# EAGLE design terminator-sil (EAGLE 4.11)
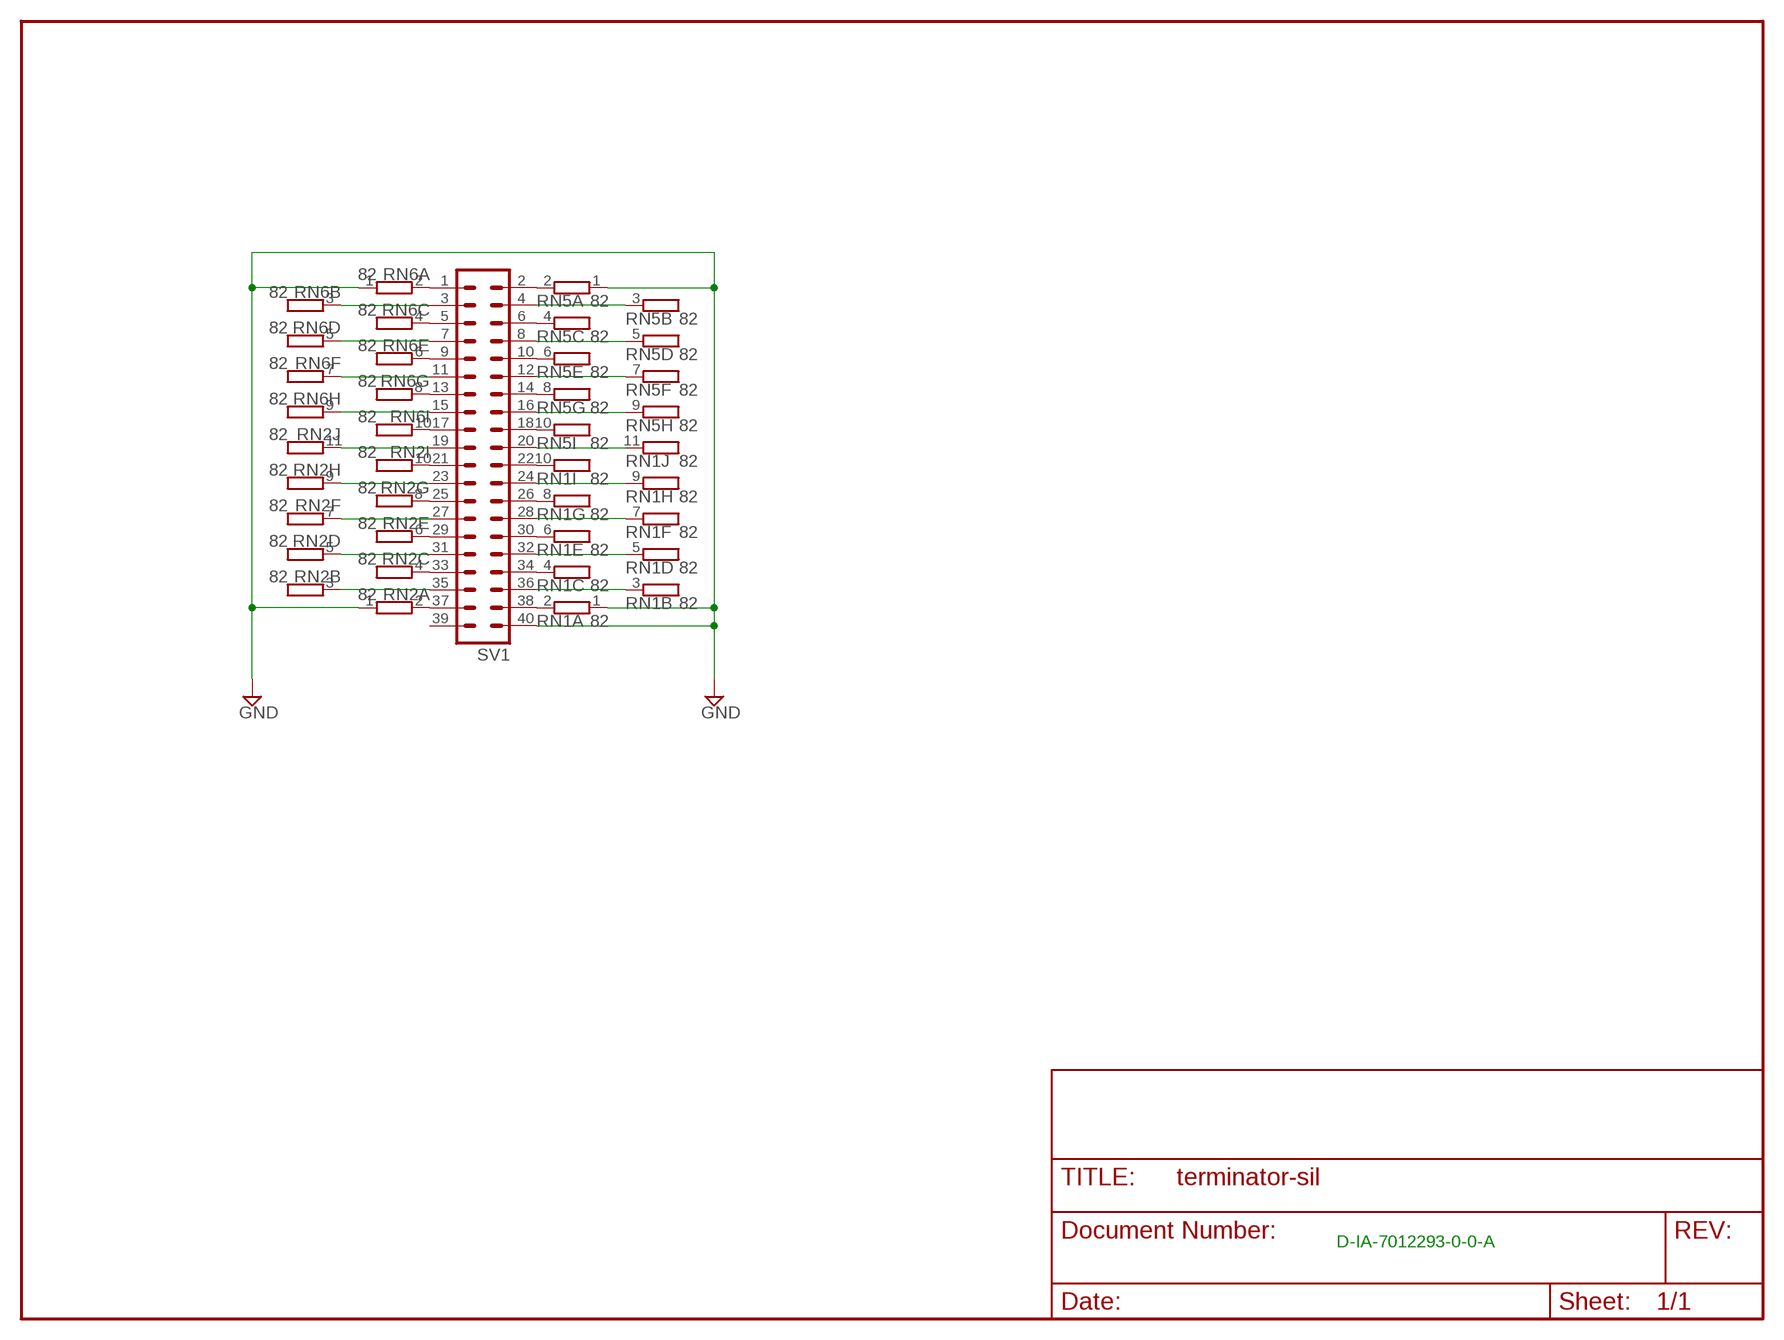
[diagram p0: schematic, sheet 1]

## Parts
RN1  82  GE10R  [SIL11]
RN2  82  GE10R  [SIL11]
RN5  82  GE09R  [SIL10]
RN6  82  GE09R  [SIL10]
SV1  MA20-2  [MA20-2]

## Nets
GND: RN1.1 RN2.1 RN5.1 RN6.1 SV1.40
N$1: RN1.2 SV1.38
N$2: RN1.3 SV1.36
N$3: RN1.4 SV1.34
N$4: RN1.6 SV1.30
N$5: RN1.8 SV1.26
N$6: RN1.10 SV1.22
N$7: RN5.10 SV1.18
N$8: RN5.8 SV1.14
N$9: RN5.6 SV1.10
N$10: RN5.4 SV1.6
N$11: RN5.3 SV1.4
N$12: RN1.5 SV1.32
N$13: RN1.7 SV1.28
N$14: RN1.9 SV1.24
N$15: RN1.11 SV1.20
N$16: RN5.9 SV1.16
N$17: RN5.7 SV1.12
N$18: RN5.5 SV1.8
N$19: RN5.2 SV1.2
N$20: RN2.2 SV1.37
N$21: RN2.4 SV1.33
N$22: RN2.6 SV1.29
N$23: RN2.8 SV1.25
N$24: RN2.10 SV1.21
N$25: RN6.10 SV1.17
N$26: RN6.8 SV1.13
N$27: RN6.6 SV1.9
N$28: RN6.4 SV1.5
N$29: RN6.2 SV1.1
N$31: RN6.3 SV1.3
N$32: RN6.5 SV1.7
N$33: RN6.7 SV1.11
N$34: RN6.9 SV1.15
N$35: RN2.3 SV1.35
N$36: RN2.5 SV1.31
N$37: RN2.7 SV1.27
N$38: RN2.9 SV1.23
N$39: RN2.11 SV1.19
Unconnected: SV1.39

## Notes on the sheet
- D-IA-7012293-0-0-A

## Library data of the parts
RN1 RN2 = resistor-sil:GE10R: SIL RESISTOR
RN5 RN6 = resistor-sil:GE09R: SIL RESISTOR
SV1 = con-lstb:MA20-2: PIN HEADER

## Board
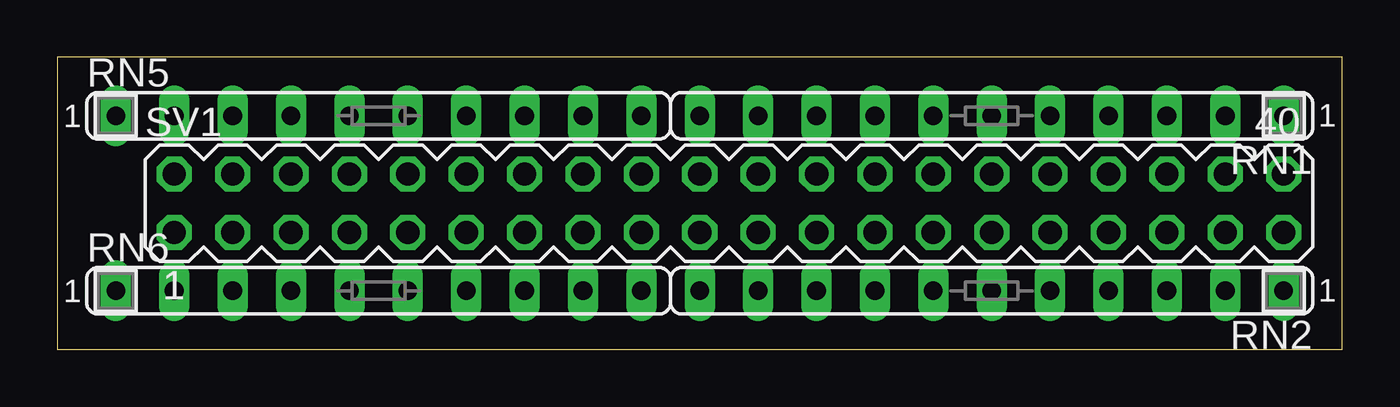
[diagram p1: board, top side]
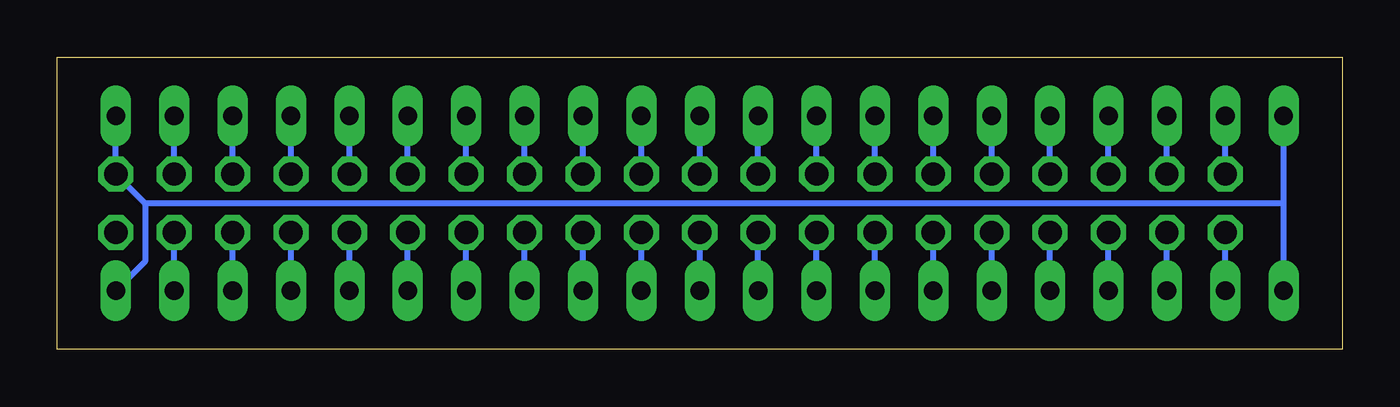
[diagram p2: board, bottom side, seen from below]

Size 55.88 x 12.7 mm. Coordinates in mm from the lower left corner, seen from the top.
Outline: 0,0 55.88,0 55.88,12.7 0,12.7 0,0
Copper layers (1*16): Top 0.035mm / dielectric 1.5mm / Bottom 0.035mm
Design rules "olimex10mil": minimum track width 10mil, minimum drill 24mil, track to track 10mil, track to pad 10mil, pad to pad 10mil, via to via 10mil, smd to smd 10mil, copper to edge 40mil, drill to drill 10mil, minimum pad ring 10mil, minimum via ring 8mil, stop-mask expansion 0mil, vias tented up to drill 0mil, thermal gap 10mil

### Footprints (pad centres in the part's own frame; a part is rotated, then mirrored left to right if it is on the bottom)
SIL11 = drill 0.813 long: 1 -12.7,0; 2 -10.16,0; 3 -7.62,0; 4 -5.08,0; 5 -2.54,0; 6 0,0; 7 2.54,0; 8 5.08,0; 9 7.62,0; 10 10.16,0; 11 12.7,0
SIL10 = drill 0.813 long: 1 -11.43,0; 2 -8.89,0; 3 -6.35,0; 4 -3.81,0; 5 -1.27,0; 6 1.27,0; 7 3.81,0; 8 6.35,0; 9 8.89,0; 10 11.43,0
MA20-2 = drill 1.016 octagon: 1 -24.13,-1.27; 2 -24.13,1.27; 3 -21.59,-1.27; 4 -21.59,1.27; 5 -19.05,-1.27; 6 -19.05,1.27; 7 -16.51,-1.27; 8 -16.51,1.27; 9 -13.97,-1.27; 10 -13.97,1.27; 11 -11.43,-1.27; 12 -11.43,1.27; 13 -8.89,-1.27; 14 -8.89,1.27; 15 -6.35,-1.27; 16 -6.35,1.27; 17 -3.81,-1.27; 18 -3.81,1.27; 19 -1.27,-1.27; 20 -1.27,1.27; 21 1.27,-1.27; 22 1.27,1.27; 23 3.81,-1.27; 24 3.81,1.27; 25 6.35,-1.27; 26 6.35,1.27; 27 8.89,-1.27; 28 8.89,1.27; 29 11.43,-1.27; 30 11.43,1.27; 31 13.97,-1.27; 32 13.97,1.27; 33 16.51,-1.27; 34 16.51,1.27; 35 19.05,-1.27; 36 19.05,1.27; 37 21.59,-1.27; 38 21.59,1.27; 39 24.13,-1.27; 40 24.13,1.27

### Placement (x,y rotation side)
RN1  40.64,10.16 180 top
RN2  40.64,2.54 180 top
RN5  13.97,10.16 0 top
RN6  13.97,2.54 0 top
SV1  29.21,6.35 0 top

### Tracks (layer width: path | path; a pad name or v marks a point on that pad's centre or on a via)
GND
  Bottom 0.254: 2.54,3.81 2.54,6.35 | 2.54,6.35 2.54,8.89 RN5.1 | RN6.1 2.54,3.81 | 52.07,6.35 52.07,3.81 RN2.1 | 52.07,6.35 SV1.40 53.34,8.89 RN1.1 | 2.54,6.35 52.07,6.35 | RN6.1 2.54,3.81 | RN6.1 2.54,3.81
N$1
  Bottom 0.254: SV1.38 50.8,8.89 RN1.2
N$2
  Bottom 0.254: SV1.36 48.26,8.89 RN1.3
N$3
  Bottom 0.254: SV1.34 45.72,8.89 RN1.4
N$4
  Bottom 0.254: SV1.30 40.64,8.89 RN1.6
N$5
  Bottom 0.254: SV1.26 35.56,8.89 RN1.8
N$6
  Bottom 0.254: SV1.22 30.48,8.89 RN1.10
N$7
  Bottom 0.254: SV1.18 25.4,8.89 RN5.10
N$8
  Bottom 0.254: SV1.14 20.32,8.89 RN5.8
N$9
  Bottom 0.254: SV1.10 15.24,8.89 RN5.6
N$10
  Bottom 0.254: SV1.6 10.16,8.89 RN5.4
N$11
  Bottom 0.254: SV1.4 7.62,8.89 RN5.3
N$12
  Bottom 0.254: SV1.32 43.18,8.89 RN1.5
N$13
  Bottom 0.254: SV1.28 38.1,8.89 RN1.7
N$14
  Bottom 0.254: SV1.24 33.02,8.89 RN1.9
N$15
  Bottom 0.254: SV1.20 27.94,8.89 RN1.11
N$16
  Bottom 0.254: SV1.16 22.86,8.89 RN5.9
N$17
  Bottom 0.254: SV1.12 17.78,8.89 RN5.7
N$18
  Bottom 0.254: SV1.8 12.7,8.89 RN5.5
N$19
  Bottom 0.254: SV1.2 5.08,8.89 RN5.2
N$20
  Bottom 0.254: SV1.37 50.8,3.81 RN2.2
N$21
  Bottom 0.254: SV1.33 45.72,3.81 RN2.4
N$22
  Bottom 0.254: SV1.29 40.64,3.81 RN2.6
N$23
  Bottom 0.254: SV1.25 35.56,3.81 RN2.8
N$24
  Bottom 0.254: SV1.21 30.48,3.81 RN2.10
N$25
  Bottom 0.254: SV1.17 25.4,3.81 RN6.10
N$26
  Bottom 0.254: SV1.13 20.32,3.81 RN6.8
N$27
  Bottom 0.254: SV1.9 15.24,3.81 RN6.6
N$28
  Bottom 0.254: SV1.5 10.16,3.81 RN6.4
N$29
  Bottom 0.254: SV1.1 5.08,3.81 RN6.2
N$31
  Bottom 0.254: SV1.3 7.62,3.81 RN6.3
N$32
  Bottom 0.254: SV1.7 12.7,3.81 RN6.5
N$33
  Bottom 0.254: SV1.11 17.78,3.81 RN6.7
N$34
  Bottom 0.254: SV1.15 22.86,3.81 RN6.9
N$35
  Bottom 0.254: SV1.35 48.26,3.81 RN2.3
N$36
  Bottom 0.254: SV1.31 43.18,3.81 RN2.5
N$37
  Bottom 0.254: SV1.27 38.1,3.81 RN2.7
N$38
  Bottom 0.254: SV1.23 33.02,3.81 RN2.9
N$39
  Bottom 0.254: SV1.19 27.94,3.81 RN2.11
